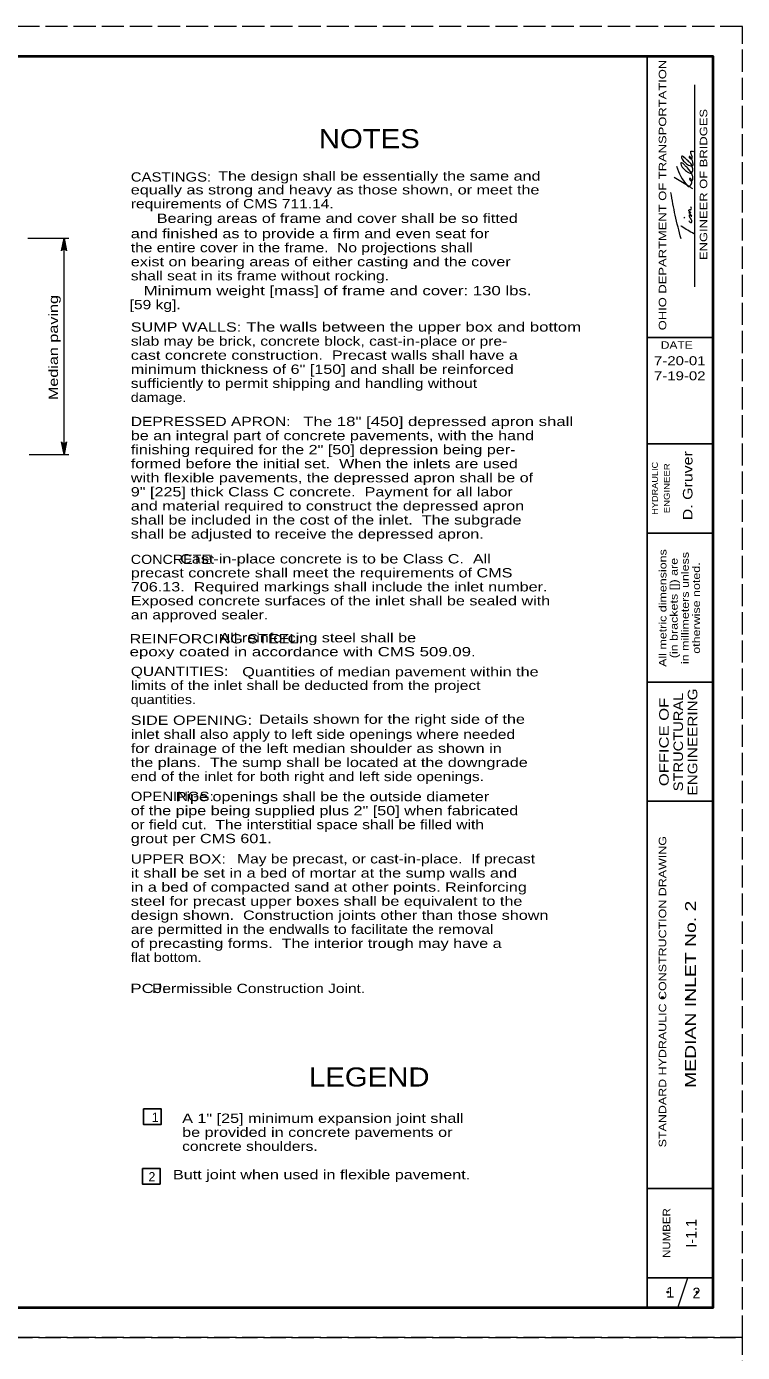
# Model space of a CAD drawing. Extents: x 339.1 to 373.1, y 1412.7 to 1456.7.
# Drawn here: x 361.04 to 373.06, y 1434.5 to 1456.75 of the extents above; entities that cross this region are included whole.
import ezdxf
from ezdxf.enums import TextEntityAlignment as Align

# ---------------------------------------------------------------- set-up
doc = ezdxf.new("R2010")
doc.units = 0
doc.header["$LTSCALE"] = 0.062
doc.header["$PDMODE"] = 32
doc.header["$PDSIZE"] = 0.031
doc.linetypes.add('LONG_DASHED', pattern=[7.5, 6, -1.5])
doc.layers.add('1', color=7, linetype='Continuous', lineweight=13)

msp = doc.modelspace()

# ---------------------------------------------------------------- linework, layer by layer
at = {"layer": '1', "lineweight": 25}
for p, q in [((341.0605, 1456.2455), (372.5605, 1456.2455)), ((371.4605, 1435.2455), (371.4605, 1456.2455)), ((372.5605, 1456.2455), (372.5605, 1435.2455)), ((372.5605, 1451.52967), (371.4605, 1451.52967)), ((372.5605, 1449.7455), (371.4605, 1449.7455)), ((372.5605, 1448.2455), (371.4605, 1448.2455)), ((372.5605, 1445.7455), (371.4605, 1445.7455)), ((372.5605, 1443.7455), (371.4605, 1443.7455)), ((372.5605, 1437.2455), (371.4605, 1437.2455)), ((372.5605, 1435.7455), (371.4605, 1435.7455))]:
    msp.add_line(p, q, dxfattribs=at)
at = {"layer": '1'}
for p, q in [((372.25925, 1452.3765), (372.25925, 1455.76658)), ((372.09175, 1453.52742), (372.08158, 1453.54667)), ((361.06308, 1453.1925), (361.75142, 1453.1925)), ((361.64275, 1452.99708), (361.67275, 1453.19325)), ((361.65533, 1453.0045), (361.67275, 1453.19325)), ((361.67275, 1449.56467), (361.67275, 1453.19325)), ((361.67275, 1453.00792), (361.67275, 1453.19325)), ((361.68642, 1453.00592), (361.67275, 1453.19325)), ((361.69983, 1452.99933), (361.67275, 1453.19325)), ((361.64558, 1449.7585), (361.67275, 1449.56467)), ((361.65908, 1449.75192), (361.67275, 1449.56467)), ((361.70275, 1449.76083), (361.67275, 1449.56467)), ((361.69017, 1449.75342), (361.67275, 1449.56467)), ((361.67275, 1449.74992), (361.67275, 1449.56467)), ((361.08742, 1449.56467), (361.75142, 1449.56467)), ((371.97717, 1435.2455), (372.14383, 1435.7455))]:
    msp.add_line(p, q, dxfattribs=at)
at = {"layer": '1', "linetype": 'LONG_DASHED'}
for points in [[(339.0605, 1434.7455), (373.0605, 1434.7455), (373.0605, 1456.7455), (339.0605, 1456.7455)], [(339.0605, 1412.7455), (373.0605, 1412.7455), (373.0605, 1434.7455), (339.0605, 1434.7455)]]:
    msp.add_lwpolyline(points, close=True, dxfattribs=at)
at = {"layer": '1', "lineweight": 25}
msp.add_lwpolyline([(372.5605, 1435.2455), (341.0605, 1435.2455), (341.0605, 1456.2455)], dxfattribs=at)
at = {"layer": '1', "lineweight": 40}
msp.add_lwpolyline([(341.0605, 1456.2455), (372.5605, 1456.2455), (372.5605, 1435.2455), (341.0605, 1435.2455)], close=True, dxfattribs=at)
at = {"layer": '1'}
for points in [[(361.62992, 1452.97908), (361.67275, 1453.19325), (361.71558, 1452.97908)], [(361.71558, 1449.77883), (361.67275, 1449.56467), (361.62992, 1449.77883)]]:
    msp.add_lwpolyline(points, dxfattribs=at)
at = {"layer": '1', "lineweight": 25}
for points in [[(363.00492, 1438.58317), (363.00492, 1438.32167), (363.3035, 1438.32167), (363.3035, 1438.58317)], [(362.98667, 1437.58425), (362.98667, 1437.3225), (363.28533, 1437.3225), (363.28533, 1437.58425)]]:
    msp.add_lwpolyline(points, close=True, dxfattribs=at)
at = {"layer": '1'}
for centre, start, end in [((361.67279, 1452.96178), 22.08782, 157.91395), ((361.6727, 1449.79609), 202.08782, 337.91395)]:
    msp.add_arc(centre, 0.04623, start, end, dxfattribs=at)
for points in [[(371.95233, 1454.4025), (372.1355, 1454.07417), (372.15067, 1454.06358), (372.16083, 1454.06358), (372.19275, 1454.08725), (372.20783, 1454.12142), (372.20283, 1454.17267), (372.18592, 1454.1945), (372.17242, 1454.1945), (372.17067, 1454.1815), (372.18083, 1454.16633), (372.19433, 1454.15792), (372.20942, 1454.15792), (372.22458, 1454.1795), (372.228, 1454.19883), (372.21775, 1454.25417), (372.1355, 1454.37458), (372.09, 1454.41925), (372.05308, 1454.45383), (372.02792, 1454.456), (372.02967, 1454.41742), (372.05483, 1454.37867), (372.12208, 1454.31633), (372.16417, 1454.29092), (372.19783, 1454.28642), (372.22117, 1454.31242), (372.228, 1454.34658), (372.22292, 1454.37233), (372.19275, 1454.4455), (372.1625, 1454.4775), (372.10192, 1454.53092), (372.07325, 1454.55675), (372.03975, 1454.572), (372.03633, 1454.544), (372.04642, 1454.51817), (372.10358, 1454.45825), (372.17425, 1454.411), (372.22625, 1454.41333), (372.22458, 1454.471), (372.21275, 1454.51392), (372.19942, 1454.53967), (372.18925, 1454.55042), (372.16583, 1454.56542), (372.16758, 1454.54833), (372.20283, 1454.52683), (372.21775, 1454.53758), (372.20467, 1454.59125), (372.19608, 1454.61917), (372.19275, 1454.63183), (372.19275, 1454.64467), (372.19275, 1454.65333), (372.21775, 1454.65117), (372.24317, 1454.65117)], [(371.9135, 1454.22025), (372.13725, 1454.08275), (372.22292, 1454.02708)], [(372.02975, 1453.18325), (371.93108, 1453.5785), (371.85983, 1453.96083)], [(372.16083, 1453.48217), (372.16908, 1453.4715), (372.20625, 1453.45858), (372.211, 1453.491), (372.18592, 1453.52742), (372.17067, 1453.56367), (372.17067, 1453.58292), (372.18592, 1453.57667), (372.19608, 1453.56583), (372.20625, 1453.5615), (372.18258, 1453.59367), (372.17067, 1453.60867), (372.16758, 1453.626), (372.191, 1453.61942), (372.18258, 1453.62808), (372.15742, 1453.65592), (372.16758, 1453.67108), (372.18433, 1453.67308), (372.19275, 1453.67108), (372.20283, 1453.69242), (372.19608, 1453.72033)], [(372.24492, 1453.26767), (372.03975, 1453.38767), (372.02417, 1453.39808)]]:
    msp.add_spline(points, degree=3, dxfattribs=at)
for p in [(371.71792, 1440.4515), (372.15075, 1440.45883), (371.80858, 1435.50925), (372.297, 1435.50825)]:
    msp.add_point(p, dxfattribs=at)

# ---------------------------------------------------------------- texts
for s, height, width, p in [('OHIO DEPARTMENT OF TRANSPORTATION', 0.125, 1.3, (371.78042, 1453.91775)), ('ENGINEER OF BRIDGES', 0.125, 1.3, (372.46875, 1454.09454)), ('D. Gruver', 0.16, 1.25, (372.22067, 1449.04)), ('HYDRAULIC', 0.1, 1.15, (371.63958, 1448.99658)), ('ENGINEER', 0.1, 1.2, (371.8405, 1448.99662)), ('All metric dimensions', 0.125, 1.25, (371.78433, 1446.98758)), ('(in brackets []) are', 0.125, 1.25, (371.97183, 1446.98758)), ('in millimeters unless', 0.125, 1.25, (372.15933, 1446.98762)), ('otherwise noted.', 0.125, 1.25, (372.34683, 1446.98758)), ('ENGINEERING', 0.16, 1.2, (372.30225, 1444.74004)), ('OFFICE OF', 0.16, 1.3, (371.82225, 1444.73996)), ('STRUCTURAL', 0.16, 1.15, (372.06225, 1444.73996)), ('STANDARD HYDRAULIC CONSTRUCTION DRAWING', 0.125, 1.25, (371.78042, 1440.54954)), ('MEDIAN INLET No. 2', 0.18, 1.35, (372.2775, 1440.50571)), ('NUMBER', 0.125, 1.15, (371.8475, 1436.49958))]:
    msp.add_text(s, height=height, rotation=90, dxfattribs=dict(at, width=width)).set_placement(p, align=Align.CENTER)
for s, height, width, p in [('NOTES', 0.32, 1.15, (366.79583, 1454.7035)), ('DATE', 0.125, 1.2, (371.95721, 1451.33825)), ('7-20-01', 0.15, 1.25, (372.00754, 1451.06275)), ('7-19-02', 0.15, 1.25, (372.00754, 1450.80967)), ('LEGEND', 0.32, 1.15, (366.79579, 1438.95825))]:
    msp.add_text(s, height=height, dxfattribs=dict(at, width=width)).set_placement(p, align=Align.CENTER)
for s, width, p in [('CASTINGS:', 1.2, (362.7925, 1454.14333)), (' The design shall be essentially the same and', 1.3, (364.1835, 1454.15917)), ('equally as strong and heavy as those shown, or meet the', 1.3, (362.79242, 1453.92808)), ('requirements of CMS 711.14.', 1.25, (362.79242, 1453.69408)), ('Bearing areas of frame and cover shall be so fitted', 1.3, (363.22858, 1453.44933)), ('and finished as to provide a firm and even seat for', 1.3, (362.7925, 1453.19325)), ('the entire cover in the frame.  No projections shall', 1.25, (362.7925, 1452.95725)), ('exist on bearing areas of either casting and the cover', 1.3, (362.7925, 1452.72125)), ('shall seat in its frame without rocking.', 1.25, (362.7925, 1452.48525)), ('   Minimum weight [mass] of frame and cover: 130 lbs.', 1.35, (362.77358, 1452.23608)), ('[59 kg].', 1.25, (362.77358, 1452.00142)), ('SUMP WALLS: ', 1.3, (362.7925, 1451.62525)), ('The walls between the upper box and bottom', 1.35, (364.73125, 1451.62683)), ('slab may be brick, concrete block, cast-in-place or pre-', 1.25, (362.7925, 1451.38925)), ('cast concrete construction.  Precast walls shall have a', 1.3, (362.7925, 1451.15325)), ('minimum thickness of 6" [150] and shall be reinforced', 1.3, (362.7925, 1450.91725)), ('sufficiently to permit shipping and handling without', 1.25, (362.7925, 1450.68125)), ('damage.', 1.15, (362.7925, 1450.44525)), ('DEPRESSED APRON:', 1.25, (362.7925, 1450.04033)), ('The 18" [450] depressed apron shall', 1.35, (365.68683, 1450.04075)), ('be an integral part of concrete pavements, with the hand', 1.3, (362.7925, 1449.80433)), ('finishing required for the 2" [50] depression being per-', 1.3, (362.7925, 1449.56833)), ('formed before the initial set.  When the inlets are used', 1.3, (362.7925, 1449.33233)), ('with flexible pavements, the depressed apron shall be of', 1.3, (362.7925, 1449.09633)), ('9" [225] thick Class C concrete.  Payment for all labor', 1.3, (362.7925, 1448.86033)), ('and material required to construct the depressed apron', 1.3, (362.7925, 1448.62433)), ('shall be included in the cost of the inlet.  The subgrade', 1.3, (362.7925, 1448.38833)), ('shall be adjusted to receive the depressed apron.', 1.3, (362.7925, 1448.15233)), ('CONCRETE:', 1.15, (362.7925, 1447.72617)), ('           Cast-in-place concrete is to be Class C.  All ', 1.3, (362.7925, 1447.73558)), ('precast concrete shall meet the requirements of CMS', 1.3, (362.7925, 1447.50092)), ('706.13.  Required markings shall include the inlet number.  ', 1.3, (362.7925, 1447.26625)), ('Exposed concrete surfaces of the inlet shall be sealed with ', 1.3, (362.7925, 1447.03158)), ('an approved sealer.', 1.25, (362.7925, 1446.79692)), ('REINFORCING STEEL:', 1.3, (362.77333, 1446.39367)), ('                    All reinforcing steel shall be', 1.3, (362.77333, 1446.41175)), ('epoxy coated in accordance with CMS 509.09.', 1.35, (362.77333, 1446.17708)), ('QUANTITIES:', 1.25, (362.7925, 1445.84767)), ('Quantities of median pavement within the', 1.3, (364.66342, 1445.84)), ('limits of the inlet shall be deducted from the project', 1.25, (362.7925, 1445.61167)), ('quantities.', 1.15, (362.7925, 1445.37567)), ('SIDE OPENING:', 1.3, (362.7925, 1445.02717)), (' Details shown for the right side of the', 1.3, (364.8715, 1445.04467)), ('inlet shall also apply to left side openings where needed', 1.25, (362.7925, 1444.79117)), ('for drainage of the left median shoulder as shown in', 1.3, (362.7925, 1444.55517)), ('the plans.  The sump shall be located at the downgrade', 1.3, (362.7925, 1444.31917)), ('end of the inlet for both right and left side openings.', 1.25, (362.7925, 1444.08317)), ('OPENINGS:', 1.2, (362.7925, 1443.74992)), ('          Pipe openings shall be the outside diameter', 1.3, (362.79242, 1443.74592)), ('of the pipe being supplied plus 2" [50] when fabricated', 1.3, (362.79242, 1443.51125)), ('or field cut.  The interstitial space shall be filled with', 1.25, (362.79242, 1443.27658)), ('grout per CMS 601.', 1.3, (362.79242, 1443.04192)), ('UPPER BOX:', 1.25, (362.7925, 1442.69942)), ('May be precast, or cast-in-place.  If precast', 1.25, (364.578, 1442.70158)), ('it shall be set in a bed of mortar at the sump walls and', 1.3, (362.7925, 1442.46342)), ('in a bed of compacted sand at other points. Reinforcing', 1.3, (362.7925, 1442.22742)), ('steel for precast upper boxes shall be equivalent to the', 1.3, (362.7925, 1441.99142)), ('design shown.  Construction joints other than those shown', 1.3, (362.7925, 1441.75542)), ('are permitted in the endwalls to facilitate the removal', 1.25, (362.7925, 1441.51942)), ('of precasting forms.  The interior trough may have a ', 1.3, (362.7925, 1441.28342)), ('flat bottom.', 1.15, (362.7925, 1441.04742)), ('     Permissible Construction Joint.', 1.25, (362.78625, 1440.52692)), ('PCJ: ', 1.35, (362.78625, 1440.52692)), ('A 1" [25] minimum expansion joint shall', 1.3, (363.65458, 1438.34817)), ('be provided in concrete pavements or', 1.3, (363.65458, 1438.1135)), ('concrete shoulders.', 1.25, (363.65458, 1437.87883)), ('  Butt joint when used in flexible pavement.', 1.3, (363.34967, 1437.40175))]:
    msp.add_text(s, height=0.156, dxfattribs=dict(at, width=width)).set_placement(p)
at = {"layer": '1', "width": 1.3}
msp.add_text('Median paving', height=0.156, rotation=90, dxfattribs=at).set_placement((361.57025, 1450.47617))
at = {"layer": '1'}
for s, p in [('1', (363.14367, 1438.36408)), ('2', (363.08867, 1437.366))]:
    msp.add_text(s, height=0.156, dxfattribs=at).set_placement(p)
msp.add_text('I-1.1', height=0.18, rotation=90, dxfattribs=at).set_placement((372.29, 1436.49583), align=Align.CENTER)
for s, p in [('1', (371.84835, 1435.41558)), ('2', (372.28779, 1435.403))]:
    msp.add_text(s, height=0.18, dxfattribs=at).set_placement(p, align=Align.CENTER)

doc.saveas('drawing.dxf')
